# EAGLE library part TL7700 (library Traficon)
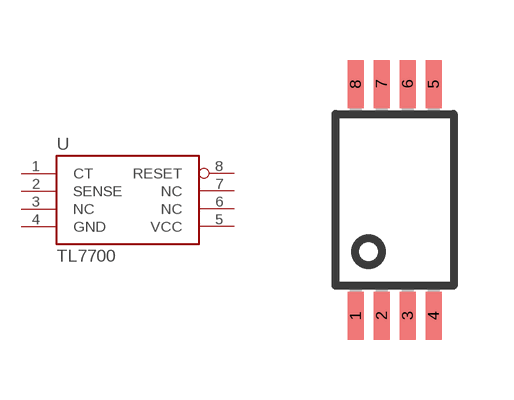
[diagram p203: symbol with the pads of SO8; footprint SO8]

Designator prefix U

## TL7700CPW  [SO8]
1  CT  pas
2  SENSE  in
3  NC  nc
4  GND  sup
5  VCC  sup
6  NC  nc
7  NC  nc
8  RESET  oc

## Footprint SO8 (pad centres in mm)
PLASTIC SMALL-OUTLINE PACKAGE, SO 8 JEDEC MO-153 Source: www.ti.com/.. slvs087l.pdf
smd 0.4 x 1.2: 1 -0.975,-2.9; 2 -0.325,-2.9; 3 0.325,-2.9; 4 0.975,-2.9; 5 0.975,2.9; 6 0.325,2.9; 7 -0.325,2.9; 8 -0.975,2.9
